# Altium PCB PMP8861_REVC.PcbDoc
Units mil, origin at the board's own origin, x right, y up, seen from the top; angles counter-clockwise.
Board outline 2300 x 1450 mil, 4 copper layers (Top Layer, MidLayer1, MidLayer2, Bottom Layer), stack 62 mil thick; 85 components, 42 nets, 258 pads, 80 vias.
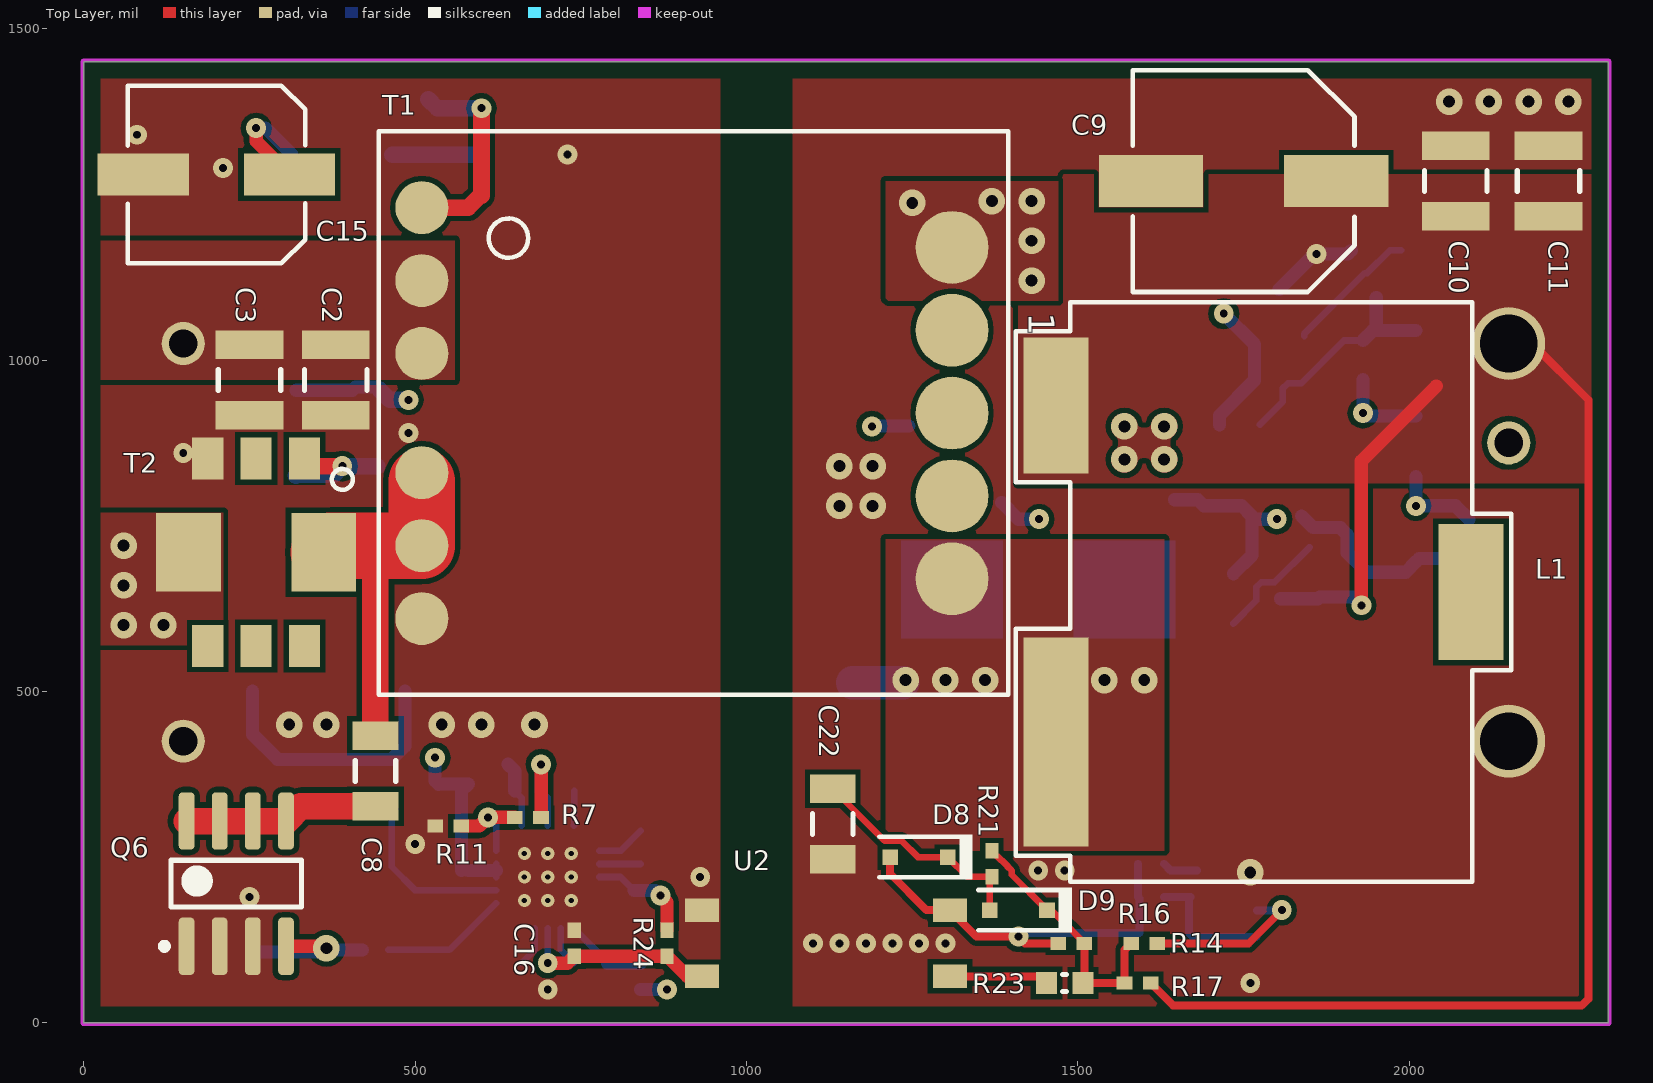
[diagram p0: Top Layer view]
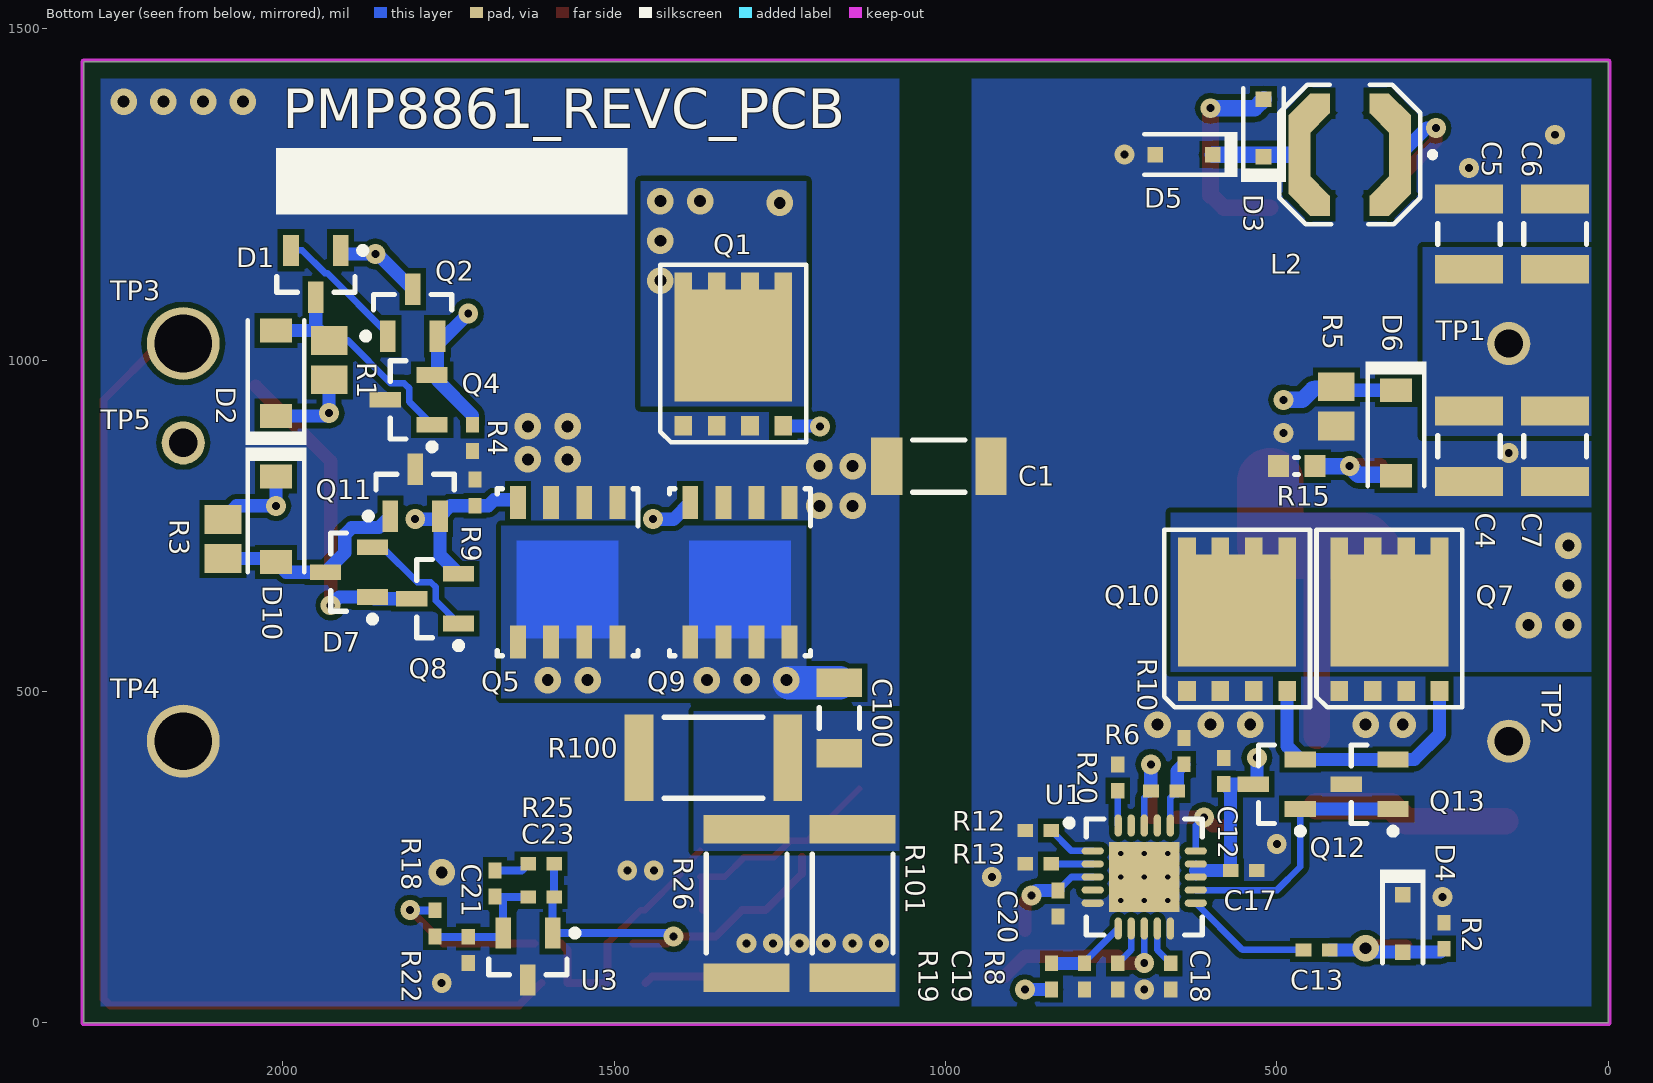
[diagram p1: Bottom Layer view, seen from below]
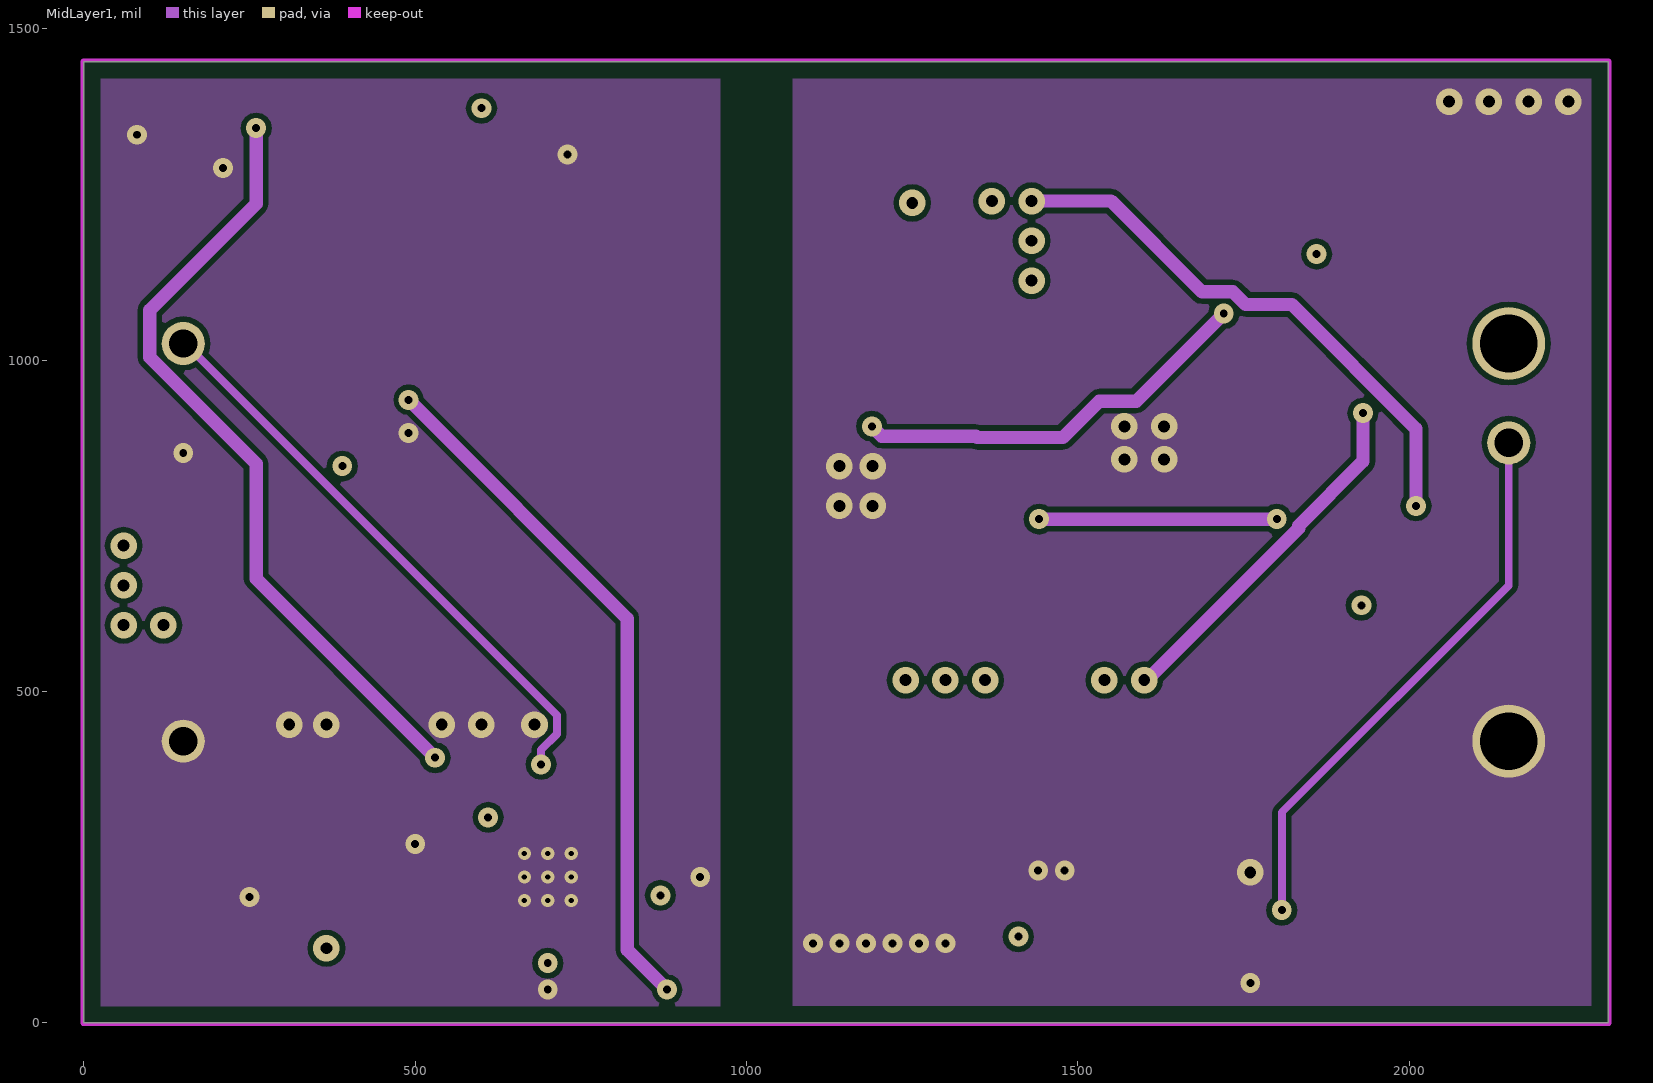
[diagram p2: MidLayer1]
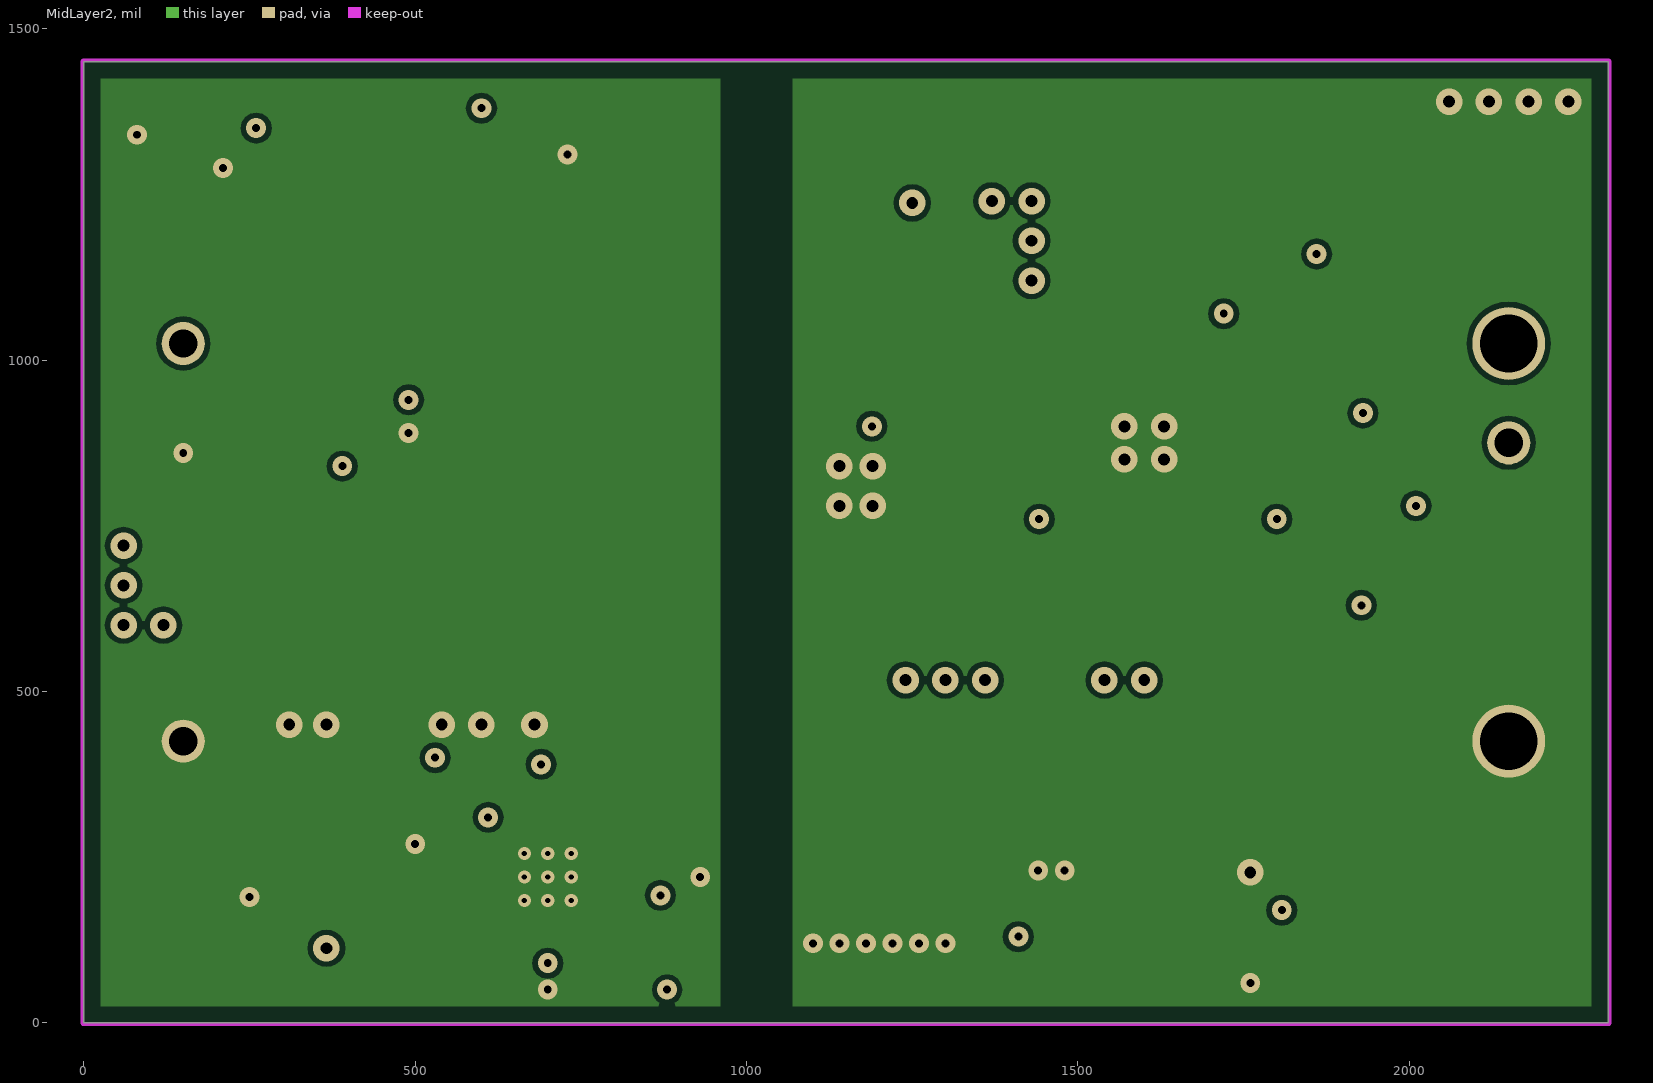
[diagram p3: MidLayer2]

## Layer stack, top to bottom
Top Solder: solder mask 0.4, Solder Resist, Dk 3.5
Top Layer: signal copper 1.4
Dielectric1: core 18.8, FR-4, Dk 4.8
MidLayer1: signal copper 1.4
Dielectric2: prepreg 18.8, FR-4, Dk 4.8
MidLayer2: signal copper 1.4
Dielectric3: core 18.8, FR-4, Dk 4.8
Bottom Layer: signal copper 1.4
Bottom Solder: solder mask 0.4, Solder Resist, Dk 3.5

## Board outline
0,0 2300,0 2300,1450 0,1450

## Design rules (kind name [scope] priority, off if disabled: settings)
AcuteAngle [All] p1: minimum=5.00000000000000E+0000 checktracksonly=FALSE
AssemblyTestPointUsage [All] p1: valid=2
BoardOutlineClearance BoardOutlineClearance_MountingHoles [OnCopper and InComponentClass('Mounting Holes')] p1: gap=25
BoardOutlineClearance BoardOutlineClearance_Poly [OnCopper and InPoly] p2: gap=25
BoardOutlineClearance [OnCopper and Not InComponentClass('Logo') and not InComponentClass('FiducialMark') and not InRegion(1000,500,4000,800)] p3: gap=25
Clearance Clearance_Keepouts [((IsTrack Or IsArc) And Not InPoly) And IsFree and IsKeepOut vs ((IsTrack Or IsArc) And Not InPoly) And IsFree and IsKeepOut] p1: gap=0
Clearance Clearance_Poly [InPolygon] p2: gap=8
Clearance [All] p3: gap=7.87
ComponentClearance ComponentClearance_MountingHoles_FiducialMarks [InComponentClass('Mounting Holes') vs InComponentClass('FiducialMark')] p1: gap=50 collisioncheckmode=3 verticalgap=10 showdistances=FALSE
ComponentClearance ComponentClearance_Shunt [InComponentClass('Header') vs InComponentClass('Shunt')] p2: gap=0 collisioncheckmode=3 verticalgap=0 showdistances=FALSE
ComponentClearance ComponentClearance_Logo [InComponentClass('Logo')] p3: gap=50 collisioncheckmode=3 verticalgap=10 showdistances=FALSE
ComponentClearance ComponentClearance_ScrewToNut [(HasFootprint('NY PMS 440 0025 PH')) vs (HasFootprint('Keystone_1902C'))] p4: gap=5 collisioncheckmode=3 verticalgap=10 showdistances=FALSE
ComponentClearance ComponentClearance_MountingHoles [InComponentClass('Mounting Holes')] p5: gap=250 collisioncheckmode=3 verticalgap=100000 showdistances=FALSE
ComponentClearance ComponentClearance_SmallPassives [HasFootprint('0201*') or HasFootprint('0402*') or HasFootprint('0508') or HasFootprint('0603*') or HasFootprint('0612') or HasFootprint('0805*') or HasFootprint('0815*') or HasFootprint('0830*') or HasFootprint('1206*') or HasFootprint('1210*') or HasFootprint('1808*') or HasFootprint('1812*') or HasFootprint('1825*') or HasFootprint('2010*') or HasFootprint('2220*') or HasFootprint('2225*') or HasFootprint('2512*') or HasFootprint('2728*') or HasFootprint('3518*') vs HasFootprint('0201*') or HasFootprint('0402*') or HasFootprint('0508') or HasFootprint('0603*') or HasFootprint('0612') or HasFootprint('0805*') or HasFootprint('0815*') or HasFootprint('0830*') or HasFootprint('1206*') or HasFootprint('1210*') or HasFootprint('1808*') or HasFootprint('1812*') or HasFootprint('1825*') or HasFootprint('2010*') or HasFootprint('2220*') or HasFootprint('2225*') or HasFootprint('2512*') or HasFootprint('2728*') or HasFootprint('3518*')] p6: gap=14.96 collisioncheckmode=3 verticalgap=10 showdistances=FALSE
ComponentClearance ComponentClearance_THtoSMT [IsThruComponent vs IsSMTComponent] p7: gap=15 collisioncheckmode=3 verticalgap=30 showdistances=FALSE
ComponentClearance ComponentClearance_THtoTH [IsThruComponent vs IsThruComponent] p8: gap=15 collisioncheckmode=3 verticalgap=30 showdistances=FALSE
ComponentClearance [All] p9: gap=15 collisioncheckmode=3 verticalgap=10 showdistances=FALSE
DiffPairsRouting [All] p1: maxlimit=100 minlimit=10 mostfreqgap=10 toplayer_minwidth=15 toplayer_maxwidth=15 toplayer_prefwidth=15 midlayer1_minwidth=15 midlayer1_maxwidth=15 midlayer1_prefwidth=15 midlayer2_minwidth=15 midlayer2_maxwidth=15 midlayer2_prefwidth=15 bottomlayer_minwidth=15 bottomlayer_maxwidth=15 bottomlayer_prefwidth=15 maxuncoupledlength=1000
FabricationTestPointUsage TestPointUsage [All] p1: valid=2 allowmultiple=FALSE
FabricationTestpoint Testpoint [All] p1: side=3 testpointundercomponent=TRUE minsize=40 maxsize=100 preferedsize=60 minholesize=0 maxholesize=40 preferedholesize=32 testpointgrid=1 allowsidetop=TRUE allowsidebottom=TRUE usegrid=TRUE gridtolerance=0.01
FanoutControl Fanout_LCC [IsLCC] p1: bgadir=Out bgaviamode=Centered fanoutstyle=Auto fanoutdirection=Alternating viagrid=1 // Fanout_LCC (Default Rule)
FanoutControl Fanout_BGA [IsBGA] p2: bgadir=Out bgaviamode=Centered fanoutstyle=Auto fanoutdirection=Alternating viagrid=1 // Fanout_BGA (Default Rule)
FanoutControl Fanout_Default [All] p4: bgadir=Out bgaviamode=Centered fanoutstyle=Auto fanoutdirection=Alternating viagrid=1 // Fanout_Default (Default Rule)
FanoutControl Fanout_Small [(CompPinCount < 5)] p5: bgadir=Out bgaviamode=Centered fanoutstyle=Auto fanoutdirection=OutThenIn viagrid=1 // Fanout_Small (Default Rule)
HoleSize [All] p1: absolutevalues=TRUE maxlimit=251 minlimit=7.87 maxpercent=80.000 minpercent=20.000
MinimumAnnularRing MinimumAnnularRing_ThermalPadVias [IsVia and InAnyComponent] p1: minimumring=5.91
MinimumAnnularRing [All] p2: minimumring=8
MinimumSolderMaskSliver MinimumSolderMaskSliver_Logo [InComponentClass('Logo') vs InComponentClass('Logo')] p1: minsoldermaskwidth=0.7
MinimumSolderMaskSliver [All] p2: minsoldermaskwidth=0.5
PlaneConnect [All] p1: planeconnectstyle=Direct reliefexpansion=10 reliefentries=4 reliefconductorwidth=10 reliefairgap=10
PolygonConnect [All] p1: connectstyle=Direct reliefconductorwidth=10 reliefentries=4 polygonreliefangle="90 Angle" airgapwidth=10
RoutingVias ThermalPadVias [IsVia and InAnyComponent] p1: holewidth=7.87 width=19.68 viastyle="Through Hole" minholewidth=7.87 minwidth=19.68 maxholewidth=12.99 maxwidth=23.62
RoutingVias [All] p2: holewidth=16 width=34 viastyle="Through Hole" minholewidth=7.87 minwidth=26 maxholewidth=40 maxwidth=65
SilkToSilkClearance SilkToSilkClearance_Pb-FreeLogo [(HasFootprint('Pb-Free_Overlay_Medium') OR HasFootprint('Pb-Free_Overlay_Small')) vs (HasFootprint('Pb-Free_Overlay_Medium') OR HasFootprint('Pb-Free_Overlay_Small'))] p1: silktosilkclearance=0
SilkToSilkClearance [All] p2: silktosilkclearance=1
SilkToSolderMaskClearance SilkToComponentPadClearance [IsPad and InAnycomponent] p1: minsilkscreentomaskgap=1 clearancetoexposedcopper=TRUE
SilkToSolderMaskClearance "Silk to Solder Mask Opening" [All] p2: minsilkscreentomaskgap=0 clearancetoexposedcopper=FALSE
SolderMaskExpansion [All] p1: expansion=1.97
Width [All] p1: maxlimit=100 minlimit=6 preferedwidth=10 checkconnectedcopper=TRUE
16 further rules are at their usual default settings.

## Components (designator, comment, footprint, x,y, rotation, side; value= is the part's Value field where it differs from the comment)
C1 "STD" 1808_L 1010,840 r180 bottom
C2 "GRM32ER72A225KA35L" 1210L 380,970 r270 top
C3 "GRM32ER72A225KA35L" 1210L 250,970 r270 top
C4 "GRM32ER72A225KA35L" 1210L 210,870 r270 bottom
C5 "GRM32ER72A225KA35L" 1210L 210,1190 r90 bottom
C6 "GRM32ER72A225KA35L" 1210L 80,1190 r90 bottom
C7 "GRM32ER72A225KA35L" 1210L 80,870 r270 bottom
C8 "STD" 1206L 440,380 r270 top
C9 "EEE-FK1A471P" SM_RADIAL_F 1750,1270 r180 top
C10 "STD" 1210L 2070,1270 r90 top
C11 "STD" 1210L 2210,1270 r90 top
C12 "STD" 0402L 580,380 r90 bottom
C13 "STD" 0402L 440,110 r0 bottom
C15 "EEHZA1E101XP" SM_RADIAL_6.3BMM 200,1280 r180 top
C16 "STD" 0402L 740,120 r90 top
C17 "STD" 0402L 550,230 r180 bottom
C18 "STD" 0402L 660,70 r90 bottom
C19 "STD" 0402L 790,70 r270 bottom
C20 "STD" 0402L 830,180 r270 bottom
C21 "STD" 0402L 1679.86,210.24 r90 bottom
C22 "STD" 1206L 1130,300 r270 top
C23 "STD" 0402L 1610,190 r180 bottom
C100 "STD" 1206L 1160,460 r90 bottom
D1 "BAW56-V-GS08" SOT-23L 1950,1130 r270 bottom
D2 "BAV21W-7-F" SOD-123 2010,980 r90 bottom
D3 "BAS316,115" sod-323 520,1350 r90 bottom
D4 "BAS316,115" sod-323 310,150 r270 bottom
D5 "BAS316,115" sod-323 640,1310 r0 bottom
D6 "BAV21W-7-F" SOD-123 320,890 r270 bottom
D7 "BAW56-V-GS08" SOT-23L 1900,680 r0 bottom
D8 "BAS316,115" sod-323 1260,250 r180 top
D9 "BAS316,115" sod-323 1410,170 r180 top
D10 "BAV21W-7-F" SOD-123 2010,760 r270 bottom
L1 "PA2729.802NL" IND_PA2729 1780,650 r270 top
L2 "LPS4414-105MLB" LPS4414 390,1310 r0 bottom
Q1 "CSD18533Q5A" TRANS_NexFET_Q5 1320,1010 r90 bottom
Q2 "MMBT3904" SOT-23L 1803.78,1071.58 r90 bottom
Q4 "MMBT3906" SOT-23L 1810,940 r0 bottom
Q5 "FDMS86200" TRANS_Fairchild_PQFN08A 1570,680 r270 bottom
Q6 "IRF6216TRPBF" SOIC-8 230,210 r90 top
Q7 "FDMS86201" TRANS_NexFET_Q5 330,610 r90 bottom
Q8 "MMBT3904" SOT-23L 1770,640 r0 bottom
Q9 "FDMS86200" TRANS_Fairchild_PQFN08A 1310,680 r270 bottom
Q10 "FDMS86201" TRANS_NexFET_Q5 560,610 r90 bottom
Q11 "MMBT3906" SOT-23L 1800,800 r90 bottom
Q12 "MMBT3904" SOT-23L 500,360 r0 bottom
Q13 "MMBT3906" SOT-23L 360,360 r0 bottom
R1 "STD" 0805L 1930,1000 r90 bottom
R2 "STD" 0402L 247.72,131.53 r270 bottom
R3 "STD" 0805L 2090,730 r90 bottom
R4 "STD" 0402L 1713.5,882.5 r90 bottom
R5 "STD" 0805L 410,930 r90 bottom
R6 "STD" 0402L 670,350 r0 bottom
R7 "STD" 0402L 670,310 r0 top
R8 "STD" 0402L 740,70 r90 bottom
R9 "STD" 0402L 1710,800 r270 bottom
R10 "STD" 0402L 640,410 r270 bottom
R11 "STD" 0402L 550,297.01 r0 top
R12 "STD" 0402L 860,290 r180 bottom
R13 "STD" 0402L 860,240 r180 bottom
R14 "STD" 0402L 1600,120 r180 top
R15 "STD" 0603L 470,840 r180 bottom
R16 "STD" 0402L 1490,120 r0 top
R17 "STD" 0402L 1590,60 r0 top
R18 "STD" 0402L 1770,150 r90 bottom
R19 "STD" 0402L 840,70 r90 bottom
R20 "STD" 0402L 740,370 r270 bottom
R21 "STD" 0402L 1370,240 r90 top
R22 "STD" 0402L 1720,110 r90 bottom
R23 "STD" 0603L 1480,60 r0 top
R24 "STD" 0402L 880,120 r90 top
R25 "STD" 0402L 1610,240 r180 bottom
R26 "CRCW251233R0JNEG" 2512L 1300,180 r270 bottom
R100 "CRCW251233R0JNEG" 2512L 1350,400 r0 bottom
R101 "CRCW251233R0JNEG" 2512L 1140,180 r270 bottom
T1 "PA0801.004NL" PA08XX 920,920 r0 top
T2 "CST2-100L" XFMR_COILCRAFT_8X8p13MM6P 260,710 r270 top
TP1 "Suggest using a net name here" CONN_8600-0-05-80-00-00-03-0 150,1025 r180 bottom locked
TP2 "Suggest using a net name here" CONN_8600-0-05-80-00-00-03-0 150,425 r90 bottom locked
TP3 "Suggest using a net name here" CONN_8952-0-05-80-00-00-03-0 2150,1025 r180 bottom locked
TP4 "Suggest using a net name here" CONN_8952-0-05-80-00-00-03-0 2150,425 r180 bottom locked
TP5 "Suggest using a net name here" CONN_8600-0-05-80-00-00-03-0 2150,875 r90 bottom locked
U1 "UCC2897ARGPR" RGP0020D 700,220 r180 bottom
U2 "VOL618A-2T" SOP254P1020X230-4 1120,120 r180 top
U3 "TL431AIDBZ" DBZ0003A_L 1630,100 r270 bottom

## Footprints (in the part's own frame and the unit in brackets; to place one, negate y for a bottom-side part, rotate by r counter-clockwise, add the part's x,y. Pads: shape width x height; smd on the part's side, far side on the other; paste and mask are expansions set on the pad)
0402L [mm] "0402 from SM-752 data"
  rect 0.6x0.5 smd: 1(-0.5,0) 2(0.5,0)
  body extent -0.55,-0.3 0.55,0.3, height 0.6
0603L [mm] "0603 from SM-752 data"
  rect 0.8x0.85 smd: 1(-0.7,0) 2(0.7,0)
  silkscreen extent -0.07,-0.33 0.07,0.33, body extent -0.87,-0.47 0.87,0.47, height 0.85
0805L [mm] "0805 from SM-752 data"
  rect 1.1x1.4 smd: 1(-0.75,0) 2(0.75,0)
  body extent -1.1,-0.72 1.1,0.72, height 1.1
1206L [mm] "1206 from SM-752 data"
  rect 1.1x1.75 smd: 1(-1.35,0) 2(1.35,0)
  silkscreen extent -0.4,-0.77 0.4,0.77, body extent -1.7,-0.9 1.7,0.9, height 1.35
1210L [mm] "1210 from SM-752 data"
  rect 1.1x2.6 smd: 1(-1.35,0) 2(1.35,0)
  silkscreen extent -0.4,-1.2 0.4,1.2, body extent -1.7,-1.35 1.7,1.35, height 1.35
1808_L [mm] "Chip Capacitor, Body 4.6x2.0mm, IPC High Density"
  rect 1.2x2.2 smd: 1(-2,0) 2(2,0)
  silkscreen extent -1,-1 1,1, body extent -2.47,-1.2 2.47,1.2, height 2.03
2512L [mm] "Chip Resistor, Body 6.3x3.2mm, IPC High Density"
  rect 1.1x3.3 smd: 1(-2.85,0) 2(2.85,0)
  silkscreen extent -1.9,-1.55 1.9,1.55, body extent -3.22,-1.67 3.22,1.67, height 0.71
CONN_8600-0-05-80-00-00-03-0 [mil] "Mill-Max"
  round 65 hole 43: 1(0,0)
  body extent -36,-36 36,36, height 400
CONN_8952-0-05-80-00-00-03-0 [mil] "Mill-Max"
  round 110 hole 87: 1(0,0)
  body extent -63,-62 63,63, height 440
DBZ0003A_L [mm] "SOT23, 3-Leads, Body 2.9x1.3mm, Pitch 0.95mm, Lead Span 2.4mm, IPC High Density"
  rect 1.2x0.6 smd: 1(-0.9,0.95) 2(-0.9,-0.95) 3(0.9,0)
  silkscreen extent -1.02,-1.5 0.7,1.92, body extent -0.7,-1.52 0.7,1.52, height 1.12
IND_PA2729 [mm] "PULSE ELECTRONICS"
  rect 5.2x2.5 smd: 1(-7.15,-7.95) 3(0,7.95)
  rect 8x2.5 smd: 2(5.75,-7.95)
  silkscreen extent -11.1,-9.5 11.1,9.5, body extent -11.1,-9.52 11.1,9.52, height 12.21
LPS4414 [mm] "Coilcraft recommended land pattern Document 548-2 10/1/10"
  rect 0.85x3 smd: 1(-1.925,0) 2(1.925,0)
  rect 1.202x1.07 smd rot 135: 1(-1.55,-1.55) 2(1.55,1.55)
  rect 1.202x1.07 smd rot 45: 1(-1.55,1.55) 2(1.55,-1.55)
  rect 0.75x0.775 smd: 1(-1.125,-1.963) 1(-1.125,1.963) 2(1.125,-1.963) 2(1.125,1.963)
  silkscreen extent -3.26,-2.68 2.7,2.68, body extent -2.2,-2.2 2.2,2.2, height 1.42
PA08XX [mil] "Recommended land pattern for Pulse PA08xxNL series of transformers"
  round 80 smd: 1(-410,310) 2(-410,200) 3(-410,90) 4(-410,-90) 5(-410,-200) 6(-410,-310)
  round 110 smd: 7(390,-250) 8(390,-125) 9(390,0) 10(390,125) 11(390,250)
  silkscreen extent -475,-425 475,425, body extent -460,-425 460,425, height 382
RGP0020D [mm] "QFN, 20-Leads, Body 4x4mm, Pitch 0.5mm, Thermal Pad 2.7x2.7mm, TI Recommended"
  oval 0.85x0.28 smd paste-0.025 mask+0.07: 1(-1.975,1) 2(-1.975,0.5) 3(-1.975,0) 4(-1.975,-0.5) 5(-1.975,-1) 11(1.975,-1) 12(1.975,-0.5) 13(1.975,0) 14(1.975,0.5) 15(1.975,1)
  oval 0.28x0.85 smd paste-0.025 mask+0.07: 6(-1,-1.975) 7(-0.5,-1.975) 8(0,-1.975) 9(0.5,-1.975) 10(1,-1.975) 16(1,1.975) 17(0.5,1.975) 18(0,1.975) 19(-0.5,1.975) 20(-1,1.975)
  rect 2.7x2.7 smd paste-1.35 mask+0.07: 21(0,0)
  silkscreen extent -3,-2.22 2.22,2.22, body extent -2.07,-2.07 2.07,2.07, height 1
SM_RADIAL_6.3BMM [mm] "Nichicon 6.3x7.7"
  rect 3.5x1.6 smd: 1(-2.8,0) 2(2.8,0)
  silkscreen extent -3.4,-3.4 3.4,3.4, body extent -3.4,-3.4 3.4,3.4, height 8
SM_RADIAL_F [mm] "8 x 10.2mm:  Panasonic F"
  rect 4x2 smd: 1(-3.55,0) 2(3.55,0)
  silkscreen extent -4.25,-4.25 4.25,4.25, body extent -4.25,-4.25 4.25,4.25, height 10.5
SOD-123 [mm] "On Semi recommended land pattern"
  rect 0.915x1.22 smd: 1(-1.637,0) 2(1.637,0)
  silkscreen extent -2.74,-1.17 2.03,1.17, body extent -1.93,-0.9 1.93,0.9, height 1.35
sod-323 [mm] "NXP recommended land pattern"
  rect 0.6x0.6 smd paste-0.05: 1(-1.1,0) 2(1.1,0)
  silkscreen extent -2.06,-0.86 1.53,0.86, body extent -1.3,-0.67 1.3,0.68, height 1.1
SOIC-8 [mm] "duplicate of SO-8.  SOIC, 8-Leads, Body 5.0x4.0mm (max), Pitch 1.27mm, IPC Medium Density"
  rrect50% 2.2x0.6 smd: 1(-2.4,1.905) 2(-2.4,0.635) 3(-2.4,-0.635) 4(-2.4,-1.905) 5(2.4,-1.905) 6(2.4,-0.635) 7(2.4,0.635) 8(2.4,1.905)
  silkscreen extent -2.52,-2.5 0.9,2.88, body extent -3,-2.45 3,2.45, height 1.59
SOP254P1020X230-4 [mm] "VISHAY"
  rect 1.3x0.9 smd: 1(-4.75,1.27) 2(-4.75,-1.27) 3(4.75,-1.27) 4(4.75,1.27)
  body extent -3.85,-2.05 3.85,2.05, height 2.02
SOT-23L [mm] "SOT23, 3-Leads, Body 2.9x1.3mm, Pitch 0.95mm, Lead Span 2.5mm, IPC High Density"
  rect 1.2x0.6 smd: 1(-0.9,0.95) 2(-0.9,-0.95) 3(0.9,0)
  silkscreen extent -1.02,-1.5 0.7,1.92, body extent -1.16,-1.45 1.21,1.45, height 1
TRANS_Fairchild_PQFN08A [mm] "Fairchild PQFN08A recommended land pattern"
  rect 1.27x0.61 smd: 1(-2.67,1.905) 2(-2.67,0.635) 3(-2.67,-0.635) 4(-2.67,-1.905) 5(2.67,-1.905) 6(2.67,-0.635) 7(2.67,0.635) 8(2.67,1.905)
  Top Layer region: -1.215,-1.955 -1.215,1.955 2.535,1.955 2.535,-1.955
  silkscreen extent -3.2,-2.7 3.2,2.7, body extent -3.05,-2.55 3.05,2.55, height 1.11
TRANS_NexFET_Q5 [mm] "TI recommended land pattern (nominal) M0139-01"
  rect 0.75x0.675 smd mask+0.051: 1(-2.776,1.917) 2(-2.776,0.639) 3(-2.776,-0.639) 4(-2.776,-1.917)
  rect 0.655x0.675 smd mask+0.051: 5(2.776,-1.917) 6(2.776,-0.639) 7(2.776,0.639) 8(2.776,1.917)
  rect 4.295x4.51 smd paste-2.2 mask+0.051: 9(0.301,0)
  silkscreen extent -3.4,-2.8 3.4,2.8, body extent -3.05,-2.55 3.05,2.55, height 1.06
XFMR_COILCRAFT_8X8p13MM6P [mil] "XFMR, Coilcratf 8x13x5.3mm"
  rect 63x47 smd: 1(-141.5,73) 2(-141.5,0) 3(-141.5,-73) 4(141.5,-73) 5(141.5,0) 6(141.5,73)
  rect 118x98 smd: 7(0,-102) 8(0,102)
  silkscreen extent -126,114 -94,146, body extent -123,-123 123,123, height 209

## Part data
C1: library part VJ1808Y102KXEAT5Z, "CAP, CERM, 1000pF, 3kV, 1808"
C2 C3 C4 C5 C6 C7: "CAP, CERM, 2.2uF, 100V, +/-10%, X7R, 1210"
C8: library part C1206C103K5RACTU, "CAP, CERM, 250V, +/-10%, X7R, 1206"
C9: "CAP, AL, 470uF, 10V, +/-20%, 0.16 ohm, SMD"
C10 C11: library part VJ1210Y473KXGAT5Z, "CAP, CERM, 16V, +/-10%, X7R, 1210"
C12 C13 C16 C17 C18: library part 04025C132KAT2A, "CAP, CERM, 25V, +/-10%, X7R, 0402"
C15: "CAP, AL, 100uF, 25V, +/-20%, 30 ohm, SMD"
C19 C21 C23: library part 04025C132KAT2A, "CAP, CERM, 50V, +/-10%, X7R, 0402"
C20: library part 04025C132KAT2A, "CAP, CERM, 16V, +/-10%, X5R, 0402"
C22: library part C1206C103K5RACTU, "CAP, CERM, 16V, +/-10%, X7R, 1206"
C100: library part C1206C103K5RACTU, "CAP, CERM, 200V, +/-10%, NP0, 1206"
D1 D7: "Diode, Switching, 70V, 0.25A, SOT-23"
D2 D6 D10: "Diode, Switching, 200V, 0.2A, SOD-123"
D3 D4 D5 D8 D9: "Diode, Ultrafast, 100V, 0.25A, SOD-323"
L1: "Inductor, Shielded Drum Core, Ferrite, 8.3 µH, 13.3 A, 0.0051 ohm, SMD"
L2: "Inductor, Shielded Drum Core, Ferrite, 1mH, 0.11A, 16.3 ohm, SMD"
Q1: library part CSD16321Q5, "MOSFET N-CH 60V 17A 8SON"
Q2 Q8 Q12: library part "MMBT3904, Fairchild Semiconductor", "Transistor, NPN, 40V, 0.2A, SOT-23"
Q4 Q11 Q13: library part "MMBT3906, Fairchild Semiconductor", "Transistor, PNP, 40V, 0.2A, SOT-23"
Q5 Q9: "MOSFET, N-CH, 150V, 35A, PQFN08A"
Q6: library part SI4427BDY-E3, "MOSFET P-CH 150V 2.2A 8-SOIC"
Q7 Q10: library part CSD16321Q5, "MOSFET N-CH 120V POWER56"
R1 R3 R5: library part CRCW08050000Z0EA, "RES, 1%, 0.125W, 0805"
R2 R4 R6 R7 R8 R9 R10 R11 R12 R13 R14 R16 R17 R18 R19 R20 R21 R22 R24 R25: library part CRCW0402133RFKED, "RES, 1%, 0.063W, 0402"
R15 R23: library part CRCW06030000Z0EA, "RES,  1%, 0.1W, 0603"
R26 R100 R101: "RES, 33, 5%, 1 W, AEC-Q200 Grade 0, 2512"
T1: "Transformer, 153 uH, SMT"
T2: "Transformer, 2000uH, SMT"
TP1 TP2 TP5: library part 8600-0-05-80-00-00-03-0, "PCB Pin, solderless Pressfit, Tin over Nickel"
TP3 TP4: library part 8952-0-05-80-00-00-03-0, "PCB Pin, solderless Pressfit, Tin over Nickel"
U1: "Advanced Active Clamp PWM Controller with Current Control, -40 to +125 degC, 20-pin QFN (RGP), Green (RoHS & no Sb/Br)"
U2: "OPTOCOUPLR PHOTOTRANS 125% 4LSOP"
U3: "PRECISION PROGRAMMABLE REFERENCE, DBZ0003A"

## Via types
v1: diameter 30, hole 12, Top Layer to Bottom Layer, 38 vias
v2: diameter 40, hole 18, Top Layer to Bottom Layer, 33 vias
v3: diameter 19.68, hole 7.87, Top Layer to Bottom Layer, 9 vias

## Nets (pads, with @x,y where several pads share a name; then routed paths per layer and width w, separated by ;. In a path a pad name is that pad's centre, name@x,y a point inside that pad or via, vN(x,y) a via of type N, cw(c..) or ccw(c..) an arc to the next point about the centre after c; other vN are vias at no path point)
BIAS: C12.1 C15.1 C17.1 L2.1 Q12.3 U1.13 U1.14 | length 1640.2
  Top Layer w20: v1(260,1350) 260,1330.24 C15.1
  MidLayer1 w20: v1(260,1350) 260,1236 99.5,1075.5 99.5,1004.08 260,843.58 260,670 v1(530,400)
  Bottom Layer w10: U1.13 U1.14
  Bottom Layer w20: v1(260,1350) 274.21,1350 L2.1@314.21,1310 ; v1(530,400) 530,365.43 Q12.3 535.75,360.32 C12.1 569.68,350 C17.1 ; C17.1@579.68,229.84 622.24,229.84
GND: C1.1 C9.2 C10.2 C11.2 C22.2 Q1.1 Q1.2 Q1.3 Q4.3 Q5.1 Q5.2 Q5.3 Q9.1 Q9.2 Q9.3 Q11.3 R4.1 R9.1 R22.1 R26.2 R100.2 R101.2 TP4.1 U3.3
  other v1: 1760,60 1100,120 1140,120 1180,120 1220,120 1260,120 1300,120 1440,230 1480,230
  other v2: 1760,227.01 1140,780 1190,780 1140,840 1190,840 1570,850 1630,850 1570,900 1630,900 2060,1390 2120,1390 2180,1390 2240,1390
NetC8_1: C8.1 T1.4 T1.5 T2.8 | length 536
  Top Layer w40: C8.1 440,719.96 440.04,720
  Top Layer w100: T2.8 371.96,719.96 440,719.96 ; 440.04,720 T1.5 T1.4@510,817
NetC8_2: C8.2 Q6.5 Q6.6 Q6.7 Q6.8 | length 294.3
  Top Layer w40: Q6.8 Q6.7 Q6.6 Q6.5 327.36,326.85 C8.2
NetC13_1: C13.1 D4.2 Q6.4 R2.2 | length 221.4
  Top Layer w20: Q6.4 363.06,115.51 v2(366.05,112.52)
  Bottom Layer w20: R2.2@252.86,106.69 D4.2 v2@360.22,106.69 ; v2@368.57,110 C13.1
NetC13_2: C13.2 U1.11 | length 191.8
  Bottom Layer w10: C13.2 551.61,110 U1.11
NetC16_1: C16.1 R24.1 U1.8 U2.4 | length 302.1
  Top Layer w20: v1(700,90) 729.68,90 C16.1 R24.1 910.32,70 U2.4
  Bottom Layer w10: v1(700,90) U1.8
NetC18_2: C18.2 U1.9 | length 61
  Bottom Layer w10: C18.2 680.32,110 U1.9
NetC19_1: C19.1 R19.2 U1.6 | length 121.6
  Bottom Layer w10: U1.6 C19.1@790,91.61
  Bottom Layer w20: C19.1 R19.2
NetC20_1: C20.1 R24.2 U1.3 | length 160.5
  Top Layer w20: v1(870,192.28) 880,182.28 R24.2
  Bottom Layer w10: U1.3 809.68,220 C20.1
  Bottom Layer w20: C20.1 862.6,199.68 v1(870,192.28)
NetC21_1: C21.1 C23.1 R18.1 R22.2 U3.2 | length 200.3
  Bottom Layer w12: C23.1 1670,190 1667.4,187.4 U3.2 1673.15,129.69 R22.2 R18.1@1769.37,129.69
NetC21_2: C21.2 R25.1 | length 54.3
  Bottom Layer w12: R25.1 1639.76,229.92 C21.2
NetC22_1: C22.1 D8.1 D9.2 R21.1 | length 346.7
  Top Layer w10: C22.1 1208.34,274.81 1233.89,274.81 1258.7,250 D8.1 1332.99,220.32 R21.1 1366.69,217.01 D9.2
NetC23_2: C23.2 D8.2 R16.1 R25.2 U2.2 U3.1 | length 609.3
  Top Layer w12: D8.2 1216.69,224.88 1271.57,170 U2.2 1347.01,130 v1(1410,130) 1420,120 R16.1
  Bottom Layer w12: v1(1410,130) 1415.43,135.43 U3.1 C23.2@1592.6,187.72 ; C23.2 R25.2
NetC100_1: C100.1 R26.1 R100.1 R101.1
NetC100_2: C100.2 D2.1 L1.2 Q5.5 Q5.6 Q5.7 Q5.8 Q9.5 Q9.6 Q9.7 Q9.8 R1.1 T1.7 | length 740.3
  MidLayer1 w20: v2@1603.68,517.01 1833,746.33 1833,750.01 1930,847.01 v1(1930,920)
  Bottom Layer w20: v1(1930,920) R1.1 ; v1@1934.47,915.53 D2.1
  Bottom Layer w50: C100.2 v2@1236.14,513.15
  other v2: 1240,517.01 1300,517.01 1360,517.01 1540,517.01 1600,517.01
NetD1_2: D1.2 Q2.1 | length 201.8
  Bottom Layer w10: Q2.1 1841.18,1039.56 1932.8,1131.19 1936.23,1131.19 1970.47,1165.43 D1.2
NetD1_3: D1.3 D2.2 Q4.1 R1.2 | length 358.3
  Bottom Layer w10: Q4.1 1808.81,936.84 1808.81,957.2 1816.43,964.81 1836.78,964.81 1901.5,1029.53 R1.2
  Bottom Layer w20: R1.2 R1.2@1944.94,1044.47 ; D1.3 1950,1049.53 R1.2@1944.94,1044.47 ; D2.2 R1.2@1944.94,1044.47
NetD3_1: D3.1 D5.1 L2.2 | length 130.9
  Bottom Layer w25: L2.2@465.79,1310 D5.1
NetD3_2: D3.2 T1.1 | length 314.9
  Top Layer w25: T1.1 580,1230 598.15,1248.15 600,1248.15 v1(600,1380)
  Bottom Layer w25: D3.2 533.31,1380 v1(600,1380)
NetD6_1: D6.1 R5.2 R19.1 | length 1266
  MidLayer1 w20: v1(490,940) 820,610 820,110 v1(880,50)
  Bottom Layer w20: D6.1 404.94,954.47 R5.2 441.97,959.53 ; R19.1 v1@879.68,50.32
  Bottom Layer w25: 445.77,955.73 461.5,940 v1(490,940)
NetD6_2: D6.2 R15.2 T2.1 | length 173.9
  Top Layer w25: T2.1@344.5,840 v1(390,840)
  Bottom Layer w25: D6.2 321.26,826.79 376.79,826.79 v1(390,840) R15.2
NetD7_2: D7.2 Q8.1 | length 174.3
  Bottom Layer w10: Q8.1 1768.81,636.84 1768.81,657.2 1776.43,664.81 1796.78,664.81 D7.2@1849.37,717.4
NetD7_3: D7.3 D10.2 Q11.1 R3.1 | length 312.2
  Bottom Layer w20: Q11.1 1854.76,747.21 1895.64,747.21 1906.19,736.67 1906.19,709.24 D7.3 1994.47,680 D10.2 2014.94,700.47 R3.1
NetD9_1: D9.1 R14.2 R16.2 R17.1 R21.2 R23.2 | length 385.6
  Top Layer w10: R21.2 1384.56,245.13 1385.23,245.13 1392.84,237.51 1392.84,236.84 1400,229.69 1400,223.31 D9.1 1459.69,170 1486.84,142.84 1487.51,142.84 1495.13,135.23 1495.13,134.56 R16.2
  Top Layer w12: R16.2 1509.69,62.13 1511.81,60 R17.1 1570.32,110 R14.2
NetD10_1: D10.1 Q1.5 Q1.6 Q1.7 Q1.8 Q1.9 R3.2 T1.11 | length 971.8
  MidLayer1 w20: v2(1430,1240) 1550,1240 1687,1103 1733.67,1103 1753,1083.67 1823.02,1083.67 2010,896.69 v1(2010,780)
  Bottom Layer w20: D10.1 v1(2010,780) 2069.53,780 R3.2
  other v2: 1430.04,1120 1430,1180 1250,1237.01 1370,1240
NetQ1_4: Q1.4 Q2.2 Q4.2 R4.2 | length 880.3
  MidLayer1 w20: v1(1188.98,900) 1203.97,885.01 1345.99,885.01 1348,883 1477,883 1532,938 1588,938 v1(1720,1070)
  Bottom Layer w20: v1(1188.98,900) 1189.67,900.7 Q1.4 ; R4.2 1713.5,916.33 1766.38,969.21 1766.38,1023.62 v1(1720,1070)
NetQ5_4: Q5.4 Q8.2 Q9.4 Q11.2 R9.2 | length 690.8
  MidLayer1 w20: v1(1441.47,760) v1(1800,760)
  Bottom Layer w20: Q9.4 1410.12,760 v1(1441.47,760) ; Q5.4@1645.49,789.3 1680.7,789.3 1689.69,780.31 R9.2 1746.85,780.31 Q11.2 ; Q8.2 1762.6,705.43 Q11.2 ; v1(1800,760) 1767.17,760 Q11.2
NetQ7_4: Q7.4 Q10.4 Q12.2 Q13.2 | length 402.6
  Bottom Layer w20: Q7.4 254.51,435.49 292.6,397.4 Q13.2 Q12.2 484.51,417.34 Q10.4
NetQ7_5: Q7.5 Q7.6 Q7.7 Q7.8 Q7.9 Q10.5 Q10.6 Q10.7 Q10.8 Q10.9 T2.7
  other v2: 60,600 120,600 60,660 60,720
NetQ12_1: Q12.1 Q13.1 U1.12 | length 399.4
  Bottom Layer w10: Q12.1 464.57,235.43 499.68,200.32 U1.12
  Bottom Layer w20: Q13.1 Q12.1
NetR6_1: R6.1 R10.2 U1.16 | length 101.1
  Bottom Layer w10: R6.1 660.63,339.69 U1.16
  Bottom Layer w20: R10.2 650.32,380 R6.1
NetR7_1: R7.1 R11.2 U1.15 | length 141.7
  Top Layer w20: R11.2 597.01,297.01 v1(610,310) R7.1
  Bottom Layer w10: v1(610,310) 622.24,297.76 U1.15
NetR8_2: R8.2 U1.7 | length 61
  Bottom Layer w10: U1.7 719.68,110 R8.2
NetR12_2: R12.2 U1.1 | length 75.2
  Bottom Layer w10: U1.1 809.68,259.37 R12.2
NetR13_2: R13.2 U1.2 | length 62.7
  Bottom Layer w10: U1.2 840,239.68 R13.2
NetR14_1: R14.1 R18.2 TP5.1 | length 1093.1
  Top Layer w12: R14.1 1757.56,120 v1(1807.56,170)
  MidLayer1 w12: v1(1807.56,170) 1807.56,317.56 2150,660 TP5.1
  Bottom Layer w12: R18.2 1807.24,169.69 v1(1807.56,170)
NetR20_2: R20.2 U1.20 | length 52.8
  Bottom Layer w10: U1.20 740,298.39 R20.2
NetR23_1: R23.1 U2.1 | length 149.6
  Top Layer w12: U2.1 1442.44,70 R23.1
PGND: C1.2 C2.2 C3.2 C4.2 C5.2 C6.2 C7.2 C12.2 C15.2 C16.2 C17.2 C18.1 C19.2 C20.2 D4.1 D5.2 Q6.1 Q6.2 Q6.3 Q7.1 Q7.2 Q7.3 Q10.1 Q10.2 Q10.3 Q13.3 R2.1 R5.1 R8.1 R10.1 R11.1 R12.1 R13.1 R15.1 R20.1 T1.6 T2.3 TP2.1 U1.5 U1.10 U1.21 U2.3
  other v1: 700,50 250,190 930,220 500,270 150,860 490,890 210,1290 730,1310 80,1340
  other v2: 310,450 366.05,450 540,450 600,450 680,450
  other v3: 664.57,184.57 700,184.57 735.43,184.57 664.57,220 700,220 735.43,220 664.57,255.43 700,255.43 735.43,255.43
VIN: C2.1 C3.1 C4.1 C5.1 C6.1 C7.1 R6.2 R7.2 T1.2 T1.3 TP1.1 U1.18 | length 1056.7
  Top Layer w20: R7.2@690,310.31 v1(690,390)
  MidLayer1 w12: TP1.1 153.08,1025 714,464.08 714,435.92 690,411.92 v1(690,390)
  Bottom Layer w10: R6.2 700,339.69 U1.18
  Bottom Layer w20: R6.2 690,350.31 v1(690,390)
VOUT: C9.1 C10.1 C11.1 D1.1 D7.1 L1.1 Q2.3 Q8.3 R17.2 TP3.1 | length 2373.1
  Top Layer w12: R17.2 1643.69,26 2260,26 2270,36 2270,940 2185,1025 TP3.1
  Top Layer w20: v1(1927.56,630) 1927.56,847.56 2040.75,960.75
  Bottom Layer w20: Q2.3 1856.77,1160 v1(1860,1160) 1907.17,1160 D1.1 ; Q8.3 D7.1@1861.97,640 ; D7.1 1914.96,642.6 v1(1927.56,630)
pads on no net: L1.3 T1.8 T1.9 T1.10 T2.2 T2.4 T2.5 T2.6 U1.4 U1.17 U1.19

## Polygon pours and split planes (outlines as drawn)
NetC100_1 on Bottom Layer "NETC100_1_L04_P040" (solid, remove dead copper, pour order 40): 1380,470 1380,260 1070,260 1070,470
VIN on Bottom Layer "VIN_L04_P038" (solid, remove dead copper, pour order 38): 10,1170 280,1170 280,885.75 10,885.75
GND on Bottom Layer "BottomLayer-GND" (solid, remove dead copper, pour order 52): 1070,1450 1070,23.06 2288.16,23.06 2288.16,1450
PGND on Bottom Layer "Bottom Layer-PGND" (solid, remove dead copper, pour order 44): 10,1480 10,-10 960,-10 960,1480
NetQ7_5 on Bottom Layer "Bottom Layer-DRAIN" (solid, pour order 39): 20,770 660,770 660,530 20,530
NetC100_2 on Bottom Layer "Bottom Layer-Sync Drain1" (solid, remove dead copper, pour order 45): 1210,750 1210,490 1670,490 1670,750
NetD10_1 on Bottom Layer "Bottom Layer-Sync Drain2" (solid, remove dead copper, pour order 47): 1210,930 1210,1270 1460,1270 1460,930
GND on Top Layer "Top Layer-GND" (solid, remove dead copper, pour order 54): 1070,1436.87 1070,9.92 2288.16,9.92 2288.16,1436.87
PGND on Top Layer "Top Layer-PGND" (solid, remove dead copper, pour order 43): 10,1490 10,0 960,0 960,1490
VIN on Top Layer "Top Layer-VIN" (solid, remove dead copper, pour order 36): 20,1180 560,1180 560,970 20,970
NetQ7_5 on Top Layer "Top Layer-DRAIN" (solid, remove dead copper, pour order 37): 210,770 20,770 20,570 210,570
NetC100_2 on Top Layer "Top Layer-Sync Drain1" (solid, remove dead copper, pour order 46): 1210,730 1210,260 1630,260 1630,730
NetD10_1 on Top Layer "Top Layer-Sync Drain2" (solid, remove dead copper, pour order 48): 1210,1270 1210,1089.65 1470,1089.85 1470,1270
VOUT on Top Layer "Top Layer-VOUT" (solid, remove dead copper, pour order 49): 1409.8,813.78 1409.8,1280 2290,1280 2290,813.78
PGND on MidLayer1 "Mid Layer1-PGND" (solid, remove dead copper, pour order 42): 10,1450 10,-40 960,-40 960,1450
GND on MidLayer1 "Mid Layer1-GND" (solid, remove dead copper, pour order 51): 1070,1436.87 1070,9.92 2288.16,9.92 2288.16,1436.87
PGND on MidLayer2 "Mid Layer2-PGND" (solid, remove dead copper, pour order 41): 10,1445 10,-45 960,-45 960,1445
GND on MidLayer2 "Mid Layer2-GND" (solid, remove dead copper, pour order 50): 1070,1426.87 1070,-0.08 2288.16,-0.08 2288.16,1426.87

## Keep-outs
Keep-Out Layer:
  lines w5: -2.5,0 ccw(c0,0) 0,-2.5 ; -2.5,0 ccw(c0,0) 0,-2.5 ; -2.5,0 -2.5,1450 ; -2.5,1450 cw(c0,1450) 0,1452.5 ; -2.5,1450 cw(c0,1450) 0,1452.5 ; 0,-2.5 2300,-2.5 ; 0,1452.5 2300,1452.5 ; 2300,-2.5 ccw(c2300,0) 2302.5,0 ; 2300,-2.5 ccw(c2300,0) 2302.5,0 ; 2300,1452.5 cw(c2300,1450) 2302.5,1450 ; 2300,1452.5 cw(c2300,1450) 2302.5,1450 ; 2302.5,0 2302.5,1450
  text ".Layer_Name" at 577,-858.49 h60

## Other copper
Top Layer:
  text ".Layer_Name" at 577,-858.49 h60
Bottom Layer:
  text ".Layer_Name" at 577,-858.49 h60

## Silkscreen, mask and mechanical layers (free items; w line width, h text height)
Top Overlay:
  text ".Layer_Name" at 577,-858.49 h60
Bottom Overlay:
  rectangle: 1480,1220 2010,1320
  text "PMP8861_REVC_PCB" at 2000,1350 h60
  text ".Layer_Name" at 577,-858.49 h60
Top Paste:
  text ".Layer_Name" at 577,-858.49 h60
Bottom Paste:
  text ".Layer_Name" at 577,-858.49 h60
Top Solder:
  text ".Layer_Name" at 577,-858.49 h60
  text ".Layer_Name" at 577,-858.49 h60
Bottom Solder:
  text ".Layer_Name" at 577,-858.49 h60
Drill Guide:
  text ".Layer_Name" at 577,-858.49 h60
M1 Board Outline:
  the board outline again, w10
  text ".Layer_Name" at 577,-858.49 h60
M2 Board Dimensions:
  rectangle: 124.5,-410.5 499.5,-285.5
  rectangle: -0.5,-285.5 124.5,-160.5
  lines w7: -0.5,-285.5 999.5,-285.5 ; 124.5,-410.5 124.5,-160.5 ; 249.5,-410.5 249.5,-160.5 ; 499.5,-410.5 499.5,-160.5 ; 749.5,-410.5 749.5,-160.5 ; -0.5,-410.5 -0.5,-160.5 999.5,-160.5 999.5,-410.5 -0.5,-410.5
  lines w10: -0.5,-475.5 -0.5,-455.5 ; 59.5,-485.5 -0.5,-465.5 ; 59.5,-445.5 -0.5,-465.5 ; 223.58,-465.5 -0.5,-465.5 ; 775.42,-465.5 999.5,-465.5 ; 939.5,-485.5 999.5,-465.5 ; 939.5,-445.5 999.5,-465.5 ; 999.5,-475.5 999.5,-455.5
  text "1000 (mil)" at 233.58,-501.49 h60
  text ".Layer_Name" at 577,-858.49 h60
M3 3D STEP Top:
  text ".Layer_Name" at 577,-858.49 h60
M4 3D STEP Bottom:
  text ".Layer_Name" at 577,-858.49 h60
M5 Assembly Top:
  lines w10: -292,-930.17 6308,-930.17 ; -292,-726.83 6310,-726.83 ; -292,-523.5 -292,-1133.5 3713,-1133.5 6310,-1133.5 6310,-523.5 -291.5,-523.5 -291.5,-1133.5 1284,-1133.5 ; 2173,-1133.5 2173,-523.5 ; 3440,-726.83 3440,-523.5 ; 4280,-726.83 4280,-523.5 ; 4902,-1140 4902,-937.17
  text "COMPONENTS MARKED 'DNP' SHOULD NOT BE POPULATED." at 1153.5,-318.5 h60
  text "ASSEMBLY VARIANT:" at 1153,-434 h60
  text ".VariantName" at 2189,-434 h60
  text "PCB VIEWED FROM TOP SIDE" at -228.5,-655.67 h60
  text "BOARD #:" at 2248,-655.67 h60
  text ".PRJ_Number" at 2793.5,-655.67 h60
  text "REV:" at 3638,-655.67 h60
  text ".PCB_Rev" at 3929.5,-655.67 h60
  text "SVN REV:" at 4476,-655.67 h60
  text ".VersionControl_RevNumber" at 4982,-655.67 h60
  text "IGNORE ->" at -228.5,-858.49 h60
  text "PLOT NAME =" at -228.5,-1064.34 h60
  text ".plot_File_Name" at 577,-1064.34 h60
  text "GENERATED    :" at 2250,-1064.34 h60
  text ".Print_Date" at 3119.5,-1064.34 h60
  text ".Print_Time" at 3848.5,-1064.34 h60
  text "TEXAS INSTRUMENTS" at 5113,-1064.34 h60
M6 Assembly Bottom:
  lines w10: -292.5,-727.33 6309.5,-727.33 ; -290.5,-930.67 6309.5,-930.67 ; 1115.5,-1140.5 1115.5,-937.67 ; 1737.5,-727.33 1737.5,-524 ; 2577.5,-727.33 2577.5,-524 ; 3844.5,-1134 3844.5,-524 ; 4733.5,-1134 6309,-1134 6309,-524 -292.5,-524 -292.5,-1134 2304.5,-1134 6309.5,-1134 6309.5,-524
  text "COMPONENTS MARKED 'DNP' SHOULD NOT BE POPULATED." at 6102,-318 h60
  text ".VariantName" at 5058,-434 h60
  text "ASSEMBLY VARIANT:" at 6097,-434 h60
  text ".VersionControl_RevNumber" at 1035.5,-656.17 h60
  text "SVN REV:" at 1541.5,-656.17 h60
  text ".PCB_Rev" at 2088,-656.17 h60
  text "REV:" at 2379.5,-656.17 h60
  text ".PRJ_Number" at 3224,-656.17 h60
  text "BOARD #:" at 3769.5,-656.17 h60
  text "PCB VIEWED FROM BOTTOM SIDE" at 6246,-656.17 h60
  text "IGNORE ->" at 2547.85,-858.49 h60
  text "TEXAS INSTRUMENTS" at 904.5,-1064.84 h60
  text ".Print_Time" at 2169,-1064.84 h60
  text ".Print_Date" at 2898,-1064.84 h60
  text "GENERATED    :" at 3767.5,-1064.84 h60
  text ".plot_File_Name" at 5440.5,-1064.84 h60
  text "PLOT NAME =" at 6246,-1064.84 h60
M9 Title Sheet:
  drawing of 57 lines, arcs and shapes, not listed
  text "1" at 739.84,8036.5 h70
  text "2" at 3235.5,8036.5 h70
  text "3" at 5724.84,8036.5 h70
  text "4" at 8231.51,8036.5 h70
  text "5" at 10730.5,8036.5 h70
  text "6" at 13235.5,8036.5 h70
  text "A" at -416.5,6893.5 h70
  text "A" at 14383.5,6893.5 h70
  text "B" at -416.5,4513.5 h70
  text "B" at 14383.5,4513.5 h70
  text "C" at -416.5,2138.5 h70
  text "C" at 14383.5,2138.5 h70
  text "PROJECT TITLE:" at 11343.5,277.5 h45
  text ".PRJ_Title" at 11393.5,144.17 h70
  text "DESIGNED FOR:" at 11343.5,-23.5 h45
  text ".PRJ_Customer" at 11393.5,-163.5 h70
  text "D" at -416.5,-231.5 h70
  text "D" at 14383.5,-231.5 h70
  text "FILE NAME:" at 11343.5,-323.5 h45
  text ".PCB_File_Name_No_Path" at 11393.5,-443.5 h70
  text "Texas Instruments (TI) and/or its licensors do not warrant the accuracy or completeness of this specification" at 6374,-605.34 h45
  text "ENGINEER:" at 11343.5,-613.5 h45
  text "LAYOUT BY:" at 12848.5,-613.5 h45
  text "or any information contained therein. TI and/or its licensors do not warrant that this design will meet" at 6329.01,-718 h45
  text ".PRJ_Engineer" at 11393.5,-768.49 h70
  text ".PCB_Layout" at 12899,-768.49 h70
  text "the specifications, will be suitable for your application or fit for any particular purpose, or will operate in" at 6329.01,-830.67 h45
  text ".Layer_Name" at 577,-858.49 h60
  text "ALTIUM DESIGNER VERSION:" at 12848.5,-923.5 h45
  text "an implementation. TI and/or its licensors do not warrant that the design is production worthy. You should" at 6329.01,-943.33 h45
  text "completely validate and test your design implementation to confirm the system functionality for your application." at 6374,-1056 h45
  text ".print_Scale" at 11393.5,-1056.83 h70
  text ".Application_BuildNumber" at 12899,-1056.83 h70
  text "1" at 739.84,-1263.5 h70
  text "2" at 3235.5,-1263.5 h70
  text "3" at 5724.84,-1263.5 h70
  text "4" at 8231.51,-1263.5 h70
  text "5" at 10730.5,-1263.5 h70
  text "6" at 13235.5,-1263.5 h70
M10 Fab Notes:
  drawing of 207 lines, arcs and shapes, not listed
  text "DESIGN INFORMATION" at 12381.02,6810 h60
  text "(REFER ALSO ARRAY/PANEL PROFILING INFORMATION)" at 12019.46,6648.29 h60
  text "BOARD SIZE" at 11333.46,6644 h60
  text "X" at 12301.46,6516.18 h60
  text "Number of Layers :" at 11736.46,6319 h60
  text "4" at 12831.27,6309 h60
  text "MIN. TRACK WIDTH:" at 11736.46,6180 h60
  text "8" at 12832.7,6180 h60
  text "MIL" at 12987.46,6180 h60
  text "MIN. CLEARANCE:" at 11736.46,6048 h60
  text "8" at 12832.7,6048 h60
  text "MIL" at 12987.46,6048 h60
  text "MIN. VIA PAD SIZE:" at 11736.46,5916 h60
  text "24" at 12802.71,5916 h60
  text "MIL" at 12987.46,5916 h60
  text "0.05mm (2MIL)" at 12431.46,5774.29 h60
  text "MINIMUM ANNULAR RING" at 11407.23,5770 h60
  text "EXTERNAL" at 13139.46,5770 h60
  text "PER" at 11607.23,5652 h60
  text "IPC-D-275 CLASS 2 LEVEL C" at 11827.23,5652 h60
  text "MIL, HOLES" at 13315.46,5539.71 h60
  text "+/-" at 12923,5539 h60
  text "+/-" at 13777,5539 h60
  text "REGISTRATION TOLERANCES:" at 11407.23,5534 h60
  text "METAL" at 12607,5534 h60
  text "5" at 13183.2,5534 h60
  text "3" at 14016.2,5534 h60
  text "MIL" at 14132.46,5534 h60
  text "MATERIAL:" at 11332.46,5324.54 h60
  text "FR-4 High Tg" at 12318.9,5184.21 h60
  text "FR-4" at 11793.46,5175.64 h60
  text "X" at 12165.46,5175.64 h60
  text "OTHER" at 13241.46,5175.64 h60
  text "62 MIL (1.6mm) +/-10%" at 12073.56,5012.92 h60
  text "THICKNESS:" at 11407.23,5008.64 h60
  text "X" at 11945.4,5008.64 h60
  text "OTHER" at 13358.46,5008.64 h60
  text "TOLERANCE:" at 11407.23,4850.64 h60
  text "X" at 12246.53,4850.64 h60
  text "ANSI IPC-6012 TYPE 3 CLASS 2" at 12433.48,4850.64 h60
  text "OTHER +/-" at 12433.46,4694.64 h60
  text "BOW & TWIST:" at 11407.23,4537.64 h60
  text "X" at 12246.53,4537.64 h60
  text "ANSI IPC-6012 TYPE 3 CLASS 2" at 12433.48,4537.64 h60
  text "OTHER +/-" at 12433.46,4379.13 h60
  text "COPPER THICKNESS (FINISHED):" at 11332.46,4243.64 h60
  text "1.4MIL (1oz)" at 12212.46,4090.92 h60
  text "2MIL (1.4oz)" at 12979.46,4090.92 h60
  text "2.8MIL (2oz)" at 13706.46,4090.92 h60
  text "OUTER:" at 11689.46,4086.64 h60
  text "X" at 12084,4086 h60
  text "1.4MIL (1oz)" at 12212.46,3933.92 h60
  text "2.8MIL (2oz)" at 12979.46,3933.92 h60
  text "N/A" at 13706,3934.29 h60
  text "INNER SIGNAL:" at 11400.38,3929.64 h60
  text "X" at 12085.42,3929.64 h60
  text "DRILLING:" at 11332.46,3790.64 h60
  text "REFERENCE:" at 11407.23,3673.64 h60
  text "X" at 12055.46,3673.64 h60
  text "AS SHOWN" at 12242.46,3673.64 h60
  text "X" at 12956.46,3673.64 h60
  text "NC_DRILL FILES" at 13093.46,3673.64 h60
  text "PTH MIN COPPER THICKNESS:" at 11407.23,3515.64 h60
  text "X" at 12757.46,3515.64 h60
  text "1MIL" at 12894.46,3515.64 h60
  text "OTHER" at 13391.46,3515.64 h60
  text "BOARD FINISH:" at 11332.46,3356.64 h60
  text "SILKSCREEN:" at 11487.68,3238.64 h60
  text "X" at 12436.46,3238.64 h60
  text "TOP" at 12562.46,3238.64 h60
  text "X" at 12946.46,3238.64 h60
  text "BOTTOM" at 13073.46,3238.64 h60
  text "SILKSCREEN COLOR:" at 11487.68,3071.64 h60
  text "X" at 12435.42,3071.64 h60
  text "WHITE" at 12562.46,3071.64 h60
  text "OTHER" at 13073.46,3071.64 h60
  text "SOLDER RESIST COLOR:" at 11487.68,2901.64 h60
  text "X" at 12055.42,2742.44 h60
  text "GREEN" at 12182.46,2742.44 h60
  text "BLUE" at 12773.46,2742.44 h60
  text "OTHER" at 13311.46,2742.44 h60
  text "IMMERSION GOLD (ENIG)" at 12393.46,2553.92 h60
  text "SURFACE FINISH:" at 11332.46,2549.64 h60
  text "X" at 12206.51,2549.64 h60
  text "IMM. TIN/SILVER OR EQUIV" at 11662,2392.64 h60
  text "OTHER" at 13093.46,2392.64 h60
  text "ARRAY/PANEL:" at 11332.46,2213.64 h60
  text "CUT AND TRIM PER MECH LAYER 1" at 12393.46,2209.35 h60
  text "N.C. ROUTE" at 12393.46,2057.64 h60
  text "X" at 13072.46,2057.64 h60
  text "V. SCORE" at 13259.46,2057.64 h60
  text "CERTIFICATION:" at 11332.46,1920.64 h60
  text "MATERIALS AND WORKMANSHIP FOR ALL PCBS" at 12057.46,1920.64 h60
  text "TO MEET OR EXCEED THE REQUIREMENTS OF:" at 12057.46,1822.64 h60
  text "X" at 11683.96,1686.13 h60
  text "ANSI IPC-A-600F CLASS ->" at 11822.96,1686.13 h60
  text "X" at 13462.02,1686.13 h60
  text "2" at 13580.96,1686.14 h60
  text "1" at 13265.96,1684.64 h60
  text "3" at 13934.96,1684.64 h60
  text "X" at 11686.02,1526.64 h60
  text "UL 94V-0" at 11822.96,1526.64 h60
  text "X" at 12498.02,1526.64 h60
  text "RoHS" at 12634.96,1526.64 h60
  text "OTHER" at 13279.36,1526.64 h60
  text "PER ORDER" at 13676.42,1526.64 h60
  text "ADDITIONAL REQUIREMENTS:" at 11332.46,1385.64 h60
  text "MICROSECTION:" at 11407.23,1270.64 h60
  text "YES" at 12312.96,1270.64 h60
  text "X" at 12600,1120 h60
  text "REQUIRED" at 13174.46,1114.49 h60
  text "BARE BOARD ELEC. TEST:" at 11407.23,1111.64 h60
  text "NONE" at 12712.96,1111.64 h60
  text "PER ORDER" at 13766.46,1111.64 h60
  text "X" at 13760,970 h60
  text "MANUFACTURER'S ID/LOGO:" at 11407.23,954.64 h60
  text "RAIL" at 12872.96,950.35 h60
  text "METAL" at 13364.77,950.35 h60
  text "SILK" at 13876.46,950.35 h60
  text ".Layer_Name" at 577,-858.49 h60
M11 Gerber Information:
  lines w10: -292,-930.17 6308,-930.17 ; -292,-726.83 6310,-726.83 ; -292,-523.5 -292,-1133.5 3713,-1133.5 6310,-1133.5 6310,-523.5 -291.5,-523.5 -291.5,-1133.5 1284,-1133.5 ; 2173,-1133.5 2173,-523.5 ; 3440,-726.83 3440,-523.5 ; 4280,-726.83 4280,-523.5 ; 4902,-1140 4902,-937.17
  text "ALL ARTWORK VIEWED FROM TOP SIDE" at -228.5,-655.67 h60
  text "BOARD #:" at 2248,-655.67 h60
  text ".PRJ_Number" at 2793.5,-655.67 h60
  text "REV:" at 3638,-655.67 h60
  text ".PCB_Rev" at 3929.5,-655.67 h60
  text "SVN REV:" at 4476,-655.67 h60
  text ".VersionControl_RevNumber" at 4982,-655.67 h60
  text "LAYER NAME =" at -228.5,-858.49 h60
  text "PLOT NAME =" at -228.5,-1064.34 h60
  text ".plot_File_Name" at 577,-1064.34 h60
  text "GENERATED    :" at 2250,-1064.34 h60
  text ".Print_Date" at 3119.5,-1064.34 h60
  text ".Print_Time" at 3848.5,-1064.34 h60
  text "TEXAS INSTRUMENTS" at 5113,-1064.34 h60
M12 Stackup:
  lines w6: 11350,7700.5 14240,7700.5 ; 11350,7813.1 14240,7813.1 ; 11290,6976 ccw(c11326,6976) 11326,6940 14264,6940 ccw(c14264,6976) 14300,6976 14300,7914 ccw(c14264,7914) 14264,7950 11326,7950 ccw(c11326,7914) 11290,7914 11290,6976
  text "Layer Stack Up Detail for: PMP8861_REVA.PcbDoc" at 11350,7842.95 h52
  text "Layer" at 11350,7771.1 h26
  text "Gerber" at 12361.14,7771.1 h26
  text "Copper" at 13026.52,7771.1 h26
  text "Dielectric" at 13734.35,7771.1 h26
  text "Name" at 11350,7719.1 h26
  text "Document" at 12361.14,7719.1 h26
  text "Thickness" at 13026.52,7719.1 h26
  text "Material" at 13734.35,7719.1 h26
  text "Top Solder Mask" at 11350,7644.9 h36
  text "(.GTS)" at 12361.14,7644.9 h36
  text "Solder Resist" at 13734.35,7644.9 h36
  text "Top Layer" at 11350,7539.69 h36
  text "(.GTL)" at 12361.14,7539.69 h36
  text "1.4mil" at 13026.52,7539.69 h36
  text "FR-4" at 13734.35,7487.08 h36
  text "MidLayer1" at 11350,7434.48 h36
  text "(.G1)" at 12361.14,7434.48 h36
  text "1.4mil" at 13026.52,7434.48 h36
  text "FR-4" at 13734.35,7381.88 h36
  text "MidLayer2" at 11350,7329.27 h36
  text "(.G2)" at 12361.14,7329.27 h36
  text "1.4mil" at 13026.52,7329.27 h36
  text "FR-4" at 13734.35,7276.67 h36
  text "Bottom Layer" at 11350,7224.06 h36
  text "(.GBL)" at 12361.14,7224.06 h36
  text "1.4mil" at 13026.52,7224.06 h36
  text "Bottom Solder Mask" at 11350,7118.85 h36
  text "(.GBS)" at 12361.14,7118.85 h36
  text "Solder Resist" at 13734.35,7118.85 h36
  text ".Layer_Name" at 577,-858.49 h60
M13 Component Bodies Top:
  text ".Layer_Name" at 577,-858.49 h60
M14 Component Bodies Bottom:
  text ".Layer_Name" at 577,-858.49 h60
M15 Courtyards Top:
  text ".Layer_Name" at 577,-858.49 h60
M16 Courtyards Bottom:
  text ".Layer_Name" at 577,-858.49 h60
Drill Drawing:
  text ".legend" at 2532.5,715.5 h60
  text "Drill Table" at 2557.5,530.5 h60
  text ".Layer_Name" at 577,-858.49 h60

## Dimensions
0,0 to 2300,0 on M2 Board Dimensions
0,0 to 0,1450 on M2 Board Dimensions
